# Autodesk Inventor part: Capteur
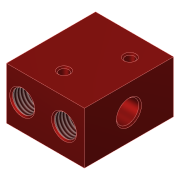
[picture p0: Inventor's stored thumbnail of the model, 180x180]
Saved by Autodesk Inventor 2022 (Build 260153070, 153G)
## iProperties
Created: 2018-06
Part Number: Capteur
Material: Aluminium 6061
Document SubType Name: Modeling
Designer: Fabian Perrée
Density: 2.7 g/cm^3
Appearance: Anodisé - Rouge
Mass: 125.414 g
Surface Area: 130.388 cm^2
Volume: 46.4496 cm^3
Author: Fabian Perrée
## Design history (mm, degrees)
sketch "Esquisse1"
  geometry: L1 (-21, 24)-(21, 24); L2 (21, 24)-(21, -24); L3 (21, -24)-(-21, -24); L4 (-21, -24)-(-21, 24); L5 (-21, 24)-(21, -24); L6 (21, 24)-(-21, -24); 1 further point
  constraints: 12 end point, 2 midpoint, 2 parallel, 1 horizontal, 1 perpendicular
  dimensions: "d0" = 48 distance of L1.end L2.end; "d1" = 42 distance of L2.end L3.end
extrude "Extrusion1" new body sketch "Esquisse1" stored distance "d2" = 28; taper "d3" = 0 deg
sketch "Esquisse2"
  geometry: L1 (21, 24)-(21, -24) reference; L2 (21, 0)-(-21, 0); L3 (-21, 24)-(21, 24) reference; L4 (21, -24)-(-21, -24) reference; L5 (0, -24)-(0, 24); L6 (12.5, 24)-(12.5, 0); L7 (18.5, 24)-(18.5, 13); L8 (18.5, 13)-(17.75, 13); L9 (16.25, 11.5)-(16.25, 10); L10 (16.25, 10)-(14.5, 10); L11 (14.5, 10)-(14.5, 0); L12 (21, -6)-(8.5, -6); L13 (8.5, -6)-(8.5, -5.25); L14 (8.5, -5.25)-(5.5, -5.25); L15 (5.5, -5.25)-(5.5, -2.5); L16 (5.5, -2.5)-(0.5, -2.5); L17 (0.5, -2.5)-(0.5, -2); L18 (0.5, -2)-(-0.5, -2); L19 (-0.5, -2)-(-0.5, -6); L20 (-0.5, -6)-(-21, -6); L21 (-21, -24)-(-21, 24) reference; L22 (21, -6)-(21, 0); L23 (-21, -6)-(-21, 0); A1 r 1.5 centre (17.75, 11.5) between (17.75, 13) and (16.25, 11.5); 2 further points
  constraints: 38 end point, 12 perpendicular, 8 point on line, 3 horizontal, 3 midpoint, 2 point on circle, 2 tangent, 1 centre point, 1 collinear, 1 parallel, 1 vertical
  dimensions: "d6" = 12 diameter of L7 L6; "d7" = 8.5 distance between parallel lines of L1 L6; "d8" = 7.5 diameter of L9 L6; "d9" = 4 diameter of L11 L6; "d10" = 11 distance of L7.start L7.end; "d11" = 3 distance of point (16.25, 13) L9.end; "d12" = 1.5 radius of A1; "d19" = 12 diameter of L12 L2; "d20" = 10.5 diameter of L14 L2; "d21" = 5 diameter of L16 L2; "d22" = 4 diameter of L18 L2; "d23" = 1 distance of L17.end L18.end; "d24" = 12 diameter of L20 L2; "d25" = 12.5 distance of L12.start L12.end; "d26" = 15.5 distance between parallel lines of L15 L1; "d27" = 20.5 distance of L19.end L20.end
revolve "Révolution1" stored, may be unused: angle "d35" = 90 deg
sketch "Esquisse3"
  geometry: C1 r 6 at (8.5, -14) reference; 2 further points
  constraints: 1 horizontal alignment
  dimensions: "d36" = 22.5 distance of C1.centre point (31, -14)
sketch "Esquisse4"
  geometry: L1 (42, 0)-(42, -28) reference; 2 further points
  constraints: 1 horizontal alignment
  dimensions: "d37" = 18 distance from line of L1 point (24, -14)
feature "Filetage1" dims "d42" = 10, "d43" = 0
feature "Réseau basé sur une esquisse1"
feature "Réseau basé sur une esquisse2"
revolve "Révolution2" stored, may be unused: angle "d38" = 90 deg
feature "Filetage2" dims "d47" = 10, "d48" = 0
sketch "Esquisse5"
  geometry: C1 r 2.5 at (-24, 14) reference; C2 r 2 at (-24, 14) reference; 2 further points
  dimensions: "d49" = 19 horizontal distance of C1.centre point (-43, 5); "d50" = 9 vertical distance of C2.centre point (-43, 5); "d51" = 19 horizontal distance of point (-5, 23) C1.centre; "d52" = 9 vertical distance of point (-5, 23) C1.centre
hole "Perçage1" sketch "Esquisse5" at (-43, 5), (-5, 23) diameter "d53" = 4.134; stored, may be unused: countersink angle "d57" = 90 deg, drill point angle "d59" = 118 deg; dims "d54" = 10, "d55" = 4, "d56" = 2, "d58" = 12.5
sketch "Esquisse6"
  geometry: L1 (21, 24)-(-21, 24) reference; L2 (21, -24)-(21, 24) reference; L3 (-21, 24)-(-21, -24) reference; L4 (-21, -24)-(21, -24) reference; 3 further points
  dimensions: "d63" = 12 distance from line of L1 point (9.5, 12); "d65" = 19 distance from line of L3 point (-2, -12); "d66" = 12 distance from line of L4 point (-2, -12); "d74" = 30.5 distance from line of L3 point (9.5, 12)
hole "Perçage2" sketch "Esquisse6" at (9.5, 12), (-2, -12) diameter "d67" = 5; stored, may be unused: countersink angle "d71" = 90 deg, drill point angle "d73" = 118 deg; dims "d68" = 10, "d69" = 4, "d70" = 2, "d72" = 12.5
chamfer "Chanfrein4" distance "d75" = 0.75; stored, may be unused: second distance "d76" = 2, angle "d77" = 45 deg
feature "Scission1"
node "Solide1"
